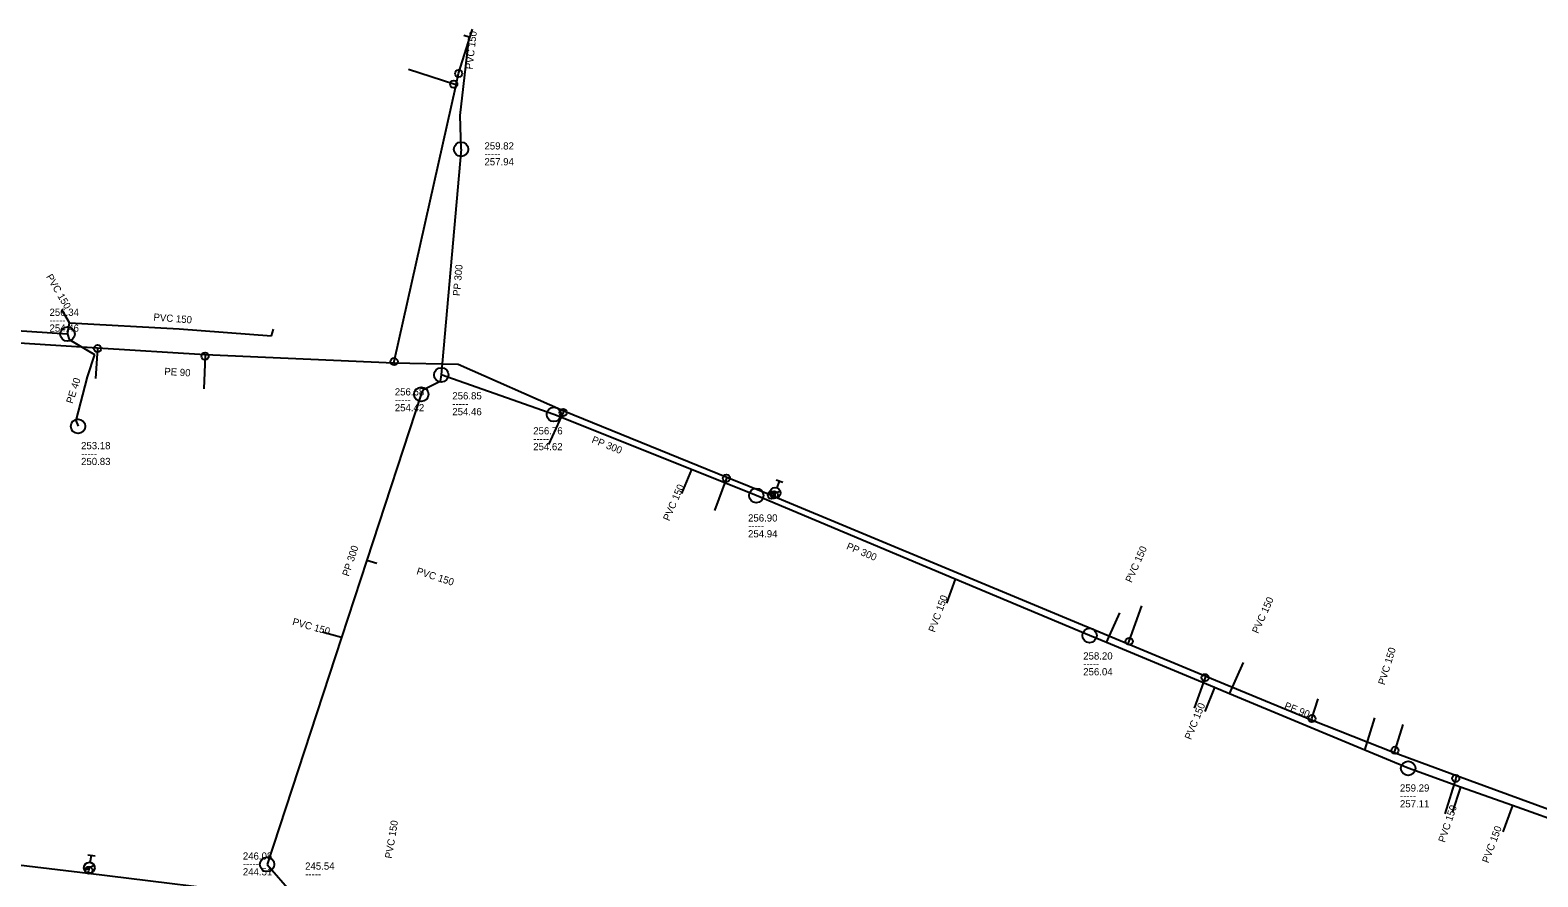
# Model space of a CAD drawing. Extents: x -771681 to -770485, y -1050143 to -1049574.
# Drawn here: x -771300.2 to -771090.5, y -1049871.3 to -1049753.6 of the extents above; entities that cross this region are included whole.
import ezdxf

# ---------------------------------------------------------------- set-up
doc = ezdxf.new("R2010")
doc.units = 0
doc.layers.add('Level 0', color=7, linetype='Continuous')

msp = doc.modelspace()

# ---------------------------------------------------------------- linework, layer by layer
at = {"layer": 'Level 0'}
for p, q in [((-771240.59, -1049759.6), (-771238.68, -1049753.42)), ((-771239.11, -1049754.55), (-771239.88, -1049754.31)), ((-771240.37, -1049765.43), (-771239.11, -1049754.55)), ((-771241.28, -1049761.08), (-771247.56, -1049759.02)), ((-771240.95, -1049761.19), (-771240.59, -1049759.6)), ((-771249.57, -1049799.67), (-771240.95, -1049761.19)), ((-771240.95, -1049761.19), (-771241.28, -1049761.08)), ((-771240.25, -1049770.14), (-771240.37, -1049765.43)), ((-771240.25, -1049770.14), (-771243.01, -1049801.52)), ((-771294.71, -1049794.27), (-771295.76, -1049792.48)), ((-771294.99, -1049795.85), (-771294.71, -1049794.27)), ((-771294.71, -1049794.27), (-771279.45, -1049795.12)), ((-771294.99, -1049795.85), (-771316.81, -1049794.4)), ((-771294.99, -1049795.85), (-771294.74, -1049796.6)), ((-771279.45, -1049795.12), (-771266.62, -1049796.09)), ((-771266.62, -1049796.09), (-771266.32, -1049795.18)), ((-771301.72, -1049797.07), (-771290.8, -1049797.76)), ((-771294.74, -1049796.6), (-771291.24, -1049798.67)), ((-771290.81, -1049797.86), (-771291.08, -1049802)), ((-771290.8, -1049797.76), (-771290.81, -1049797.86)), ((-771290.8, -1049797.76), (-771275.85, -1049798.67)), ((-771291.24, -1049798.67), (-771292.24, -1049801.78)), ((-771275.86, -1049798.92), (-771276.02, -1049803.46)), ((-771275.85, -1049798.67), (-771275.86, -1049798.92)), ((-771275.85, -1049798.67), (-771249.61, -1049799.84)), ((-771249.61, -1049799.84), (-771249.57, -1049799.67)), ((-771249.61, -1049799.84), (-771240.67, -1049800.01)), ((-771240.67, -1049800.01), (-771225.96, -1049806.53)), ((-771292.24, -1049801.78), (-771293.84, -1049807.85)), ((-771243.18, -1049802.43), (-771245.55, -1049803.64)), ((-771243.01, -1049801.52), (-771243.18, -1049802.43)), ((-771227.35, -1049807.02), (-771243.01, -1049801.52)), ((-771245.79, -1049804.22), (-771253.35, -1049827.27)), ((-771245.55, -1049803.64), (-771245.79, -1049804.22)), ((-771226.06, -1049806.75), (-771228.1, -1049811.18)), ((-771225.96, -1049806.53), (-771226.06, -1049806.75)), ((-771225.96, -1049806.53), (-771203.3, -1049815.73)), ((-771293.84, -1049807.85), (-771293.52, -1049808.67)), ((-771208.19, -1049814.7), (-771227.35, -1049807.02)), ((-771208.19, -1049814.7), (-771209.62, -1049818.03)), ((-771199.2, -1049818.3), (-771208.19, -1049814.7)), ((-771203.36, -1049815.88), (-771205.03, -1049820.36)), ((-771203.3, -1049815.73), (-771203.36, -1049815.88)), ((-771203.3, -1049815.73), (-771197.1, -1049818.25)), ((-771196.44, -1049816.11), (-771195.5, -1049816.46)), ((-771196.31, -1049817.23), (-771195.97, -1049816.29)), ((-771171.54, -1049829.92), (-771199.2, -1049818.3)), ((-771197.28, -1049818.16), (-771195.86, -1049817.7)), ((-771197.1, -1049818.25), (-771196.8, -1049818.37)), ((-771196.8, -1049818.37), (-771196.7, -1049818.2)), ((-771196.8, -1049818.37), (-771147.47, -1049838.94)), ((-771196.7, -1049818.2), (-771196.57, -1049817.93)), ((-771253.35, -1049827.27), (-771256.89, -1049838.05)), ((-771253.35, -1049827.27), (-771251.96, -1049827.72)), ((-771171.54, -1049829.92), (-771172.73, -1049833.25)), ((-771152.85, -1049837.77), (-771171.54, -1049829.92)), ((-771147.34, -1049838.58), (-771145.56, -1049833.63)), ((-771150.47, -1049838.76), (-771148.62, -1049834.61)), ((-771256.89, -1049838.05), (-771267.23, -1049869.61)), ((-771256.89, -1049838.05), (-771259.57, -1049837.31)), ((-771150.47, -1049838.76), (-771152.85, -1049837.77)), ((-771135.46, -1049845.02), (-771150.47, -1049838.76)), ((-771147.47, -1049838.94), (-771147.34, -1049838.58)), ((-771147.47, -1049838.94), (-771136.7, -1049843.41)), ((-771133.37, -1049845.89), (-771131.42, -1049841.54)), ((-771136.78, -1049843.63), (-771138.32, -1049847.89)), ((-771136.7, -1049843.41), (-771136.78, -1049843.63)), ((-771136.7, -1049843.41), (-771121.99, -1049849.51)), ((-771135.46, -1049845.02), (-771136.8, -1049848.32)), ((-771133.37, -1049845.89), (-771135.46, -1049845.02)), ((-771114.57, -1049853.74), (-771133.37, -1049845.89)), ((-771121.93, -1049849.32), (-771121.07, -1049846.59)), ((-771121.99, -1049849.51), (-771121.93, -1049849.32)), ((-771121.99, -1049849.51), (-771110.47, -1049854.05)), ((-771114.57, -1049853.74), (-771113.19, -1049849.2)), ((-771110.37, -1049853.73), (-771109.24, -1049850.17)), ((-771108.54, -1049856.24), (-771114.57, -1049853.74)), ((-771110.47, -1049854.05), (-771110.37, -1049853.73)), ((-771110.47, -1049854.05), (-771101.81, -1049857.24)), ((-771101.26, -1049858.85), (-771108.54, -1049856.24)), ((-771101.93, -1049857.64), (-771103.42, -1049862.56)), ((-771101.26, -1049858.85), (-771102.43, -1049862.37)), ((-771101.81, -1049857.24), (-771101.93, -1049857.64)), ((-771101.81, -1049857.24), (-771081.01, -1049864.88)), ((-771094.02, -1049861.43), (-771101.26, -1049858.85)), ((-771094.02, -1049861.43), (-771095.38, -1049865.08)), ((-771085.49, -1049864.48), (-771094.02, -1049861.43)), ((-771305.7, -1049869.19), (-771292.13, -1049870.85)), ((-771292.61, -1049870.42), (-771291.29, -1049869.72)), ((-771292.14, -1049868.26), (-771291.15, -1049868.43)), ((-771291.82, -1049869.33), (-771291.65, -1049868.35)), ((-771267.23, -1049869.61), (-771263.73, -1049873.6)), ((-771292.13, -1049870.85), (-771292.03, -1049870.43)), ((-771292.13, -1049870.85), (-771266.5, -1049873.98)), ((-771292.03, -1049870.43), (-771291.95, -1049870.07))]:
    msp.add_line(p, q, dxfattribs=at)
for centre, radius in [((-771241.28, -1049761.08), 0.5), ((-771240.59, -1049759.6), 0.5), ((-771240.25, -1049770.14), 1), ((-771294.99, -1049795.85), 1), ((-771290.81, -1049797.86), 0.5), ((-771275.86, -1049798.92), 0.5), ((-771249.57, -1049799.67), 0.5), ((-771243.01, -1049801.52), 1), ((-771245.79, -1049804.22), 1), ((-771227.35, -1049807.02), 1), ((-771226.06, -1049806.75), 0.5), ((-771293.52, -1049808.67), 1), ((-771203.36, -1049815.88), 0.5), ((-771199.2, -1049818.3), 1), ((-771196.57, -1049817.93), 0.75), ((-771197.1, -1049818.25), 0.5), ((-771196.7, -1049818.2), 0.5), ((-771152.85, -1049837.77), 1), ((-771147.34, -1049838.58), 0.5), ((-771136.78, -1049843.63), 0.5), ((-771121.93, -1049849.32), 0.5), ((-771110.37, -1049853.73), 0.5), ((-771108.54, -1049856.24), 1), ((-771101.93, -1049857.64), 0.5), ((-771291.95, -1049870.07), 0.75), ((-771267.23, -1049869.61), 1), ((-771292.03, -1049870.43), 0.5)]:
    msp.add_circle(centre, radius, dxfattribs=at)

# ---------------------------------------------------------------- texts
for s, rotation, p in [('PVC 150', 83.394, (-771238.67, -1049759.07)), ('PVC 150', 300.396, (-771298.01, -1049787.86)), ('PP 300', 84.974, (-771240.41, -1049790.58)), ('PVC 150', 355.676, (-771283.06, -1049793.96)), ('PE 90', 356.517, (-771281.55, -1049801.52)), ('PE 40', 72.175, (-771294.26, -1049805.59)), ('PP 300', 338.177, (-771222.18, -1049810.91)), ('PVC 150', 66.76, (-771211.3, -1049821.92)), ('PP 300', 71.821, (-771255.87, -1049829.62)), ('PP 300', 337.217, (-771186.75, -1049825.72)), ('PVC 150', 65.973, (-771147.01, -1049830.5)), ('PVC 150', 342.061, (-771246.53, -1049829.22)), ('PVC 150', 70.335, (-771174.36, -1049837.41)), ('PVC 150', 65.854, (-771129.4, -1049837.58)), ('PVC 150', 344.564, (-771263.79, -1049836.28)), ('PVC 150', 73.093, (-771111.8, -1049844.73)), ('PVC 150', 67.9, (-771138.75, -1049852.35)), ('PE 90', 338.491, (-771125.85, -1049847.91)), ('PVC 150', 71.614, (-771103.44, -1049866.64)), ('PVC 150', 80.665, (-771249.88, -1049868.85)), ('PVC 150', 69.564, (-771097.37, -1049869.5))]:
    msp.add_text(s, height=1, rotation=rotation, dxfattribs=at).set_placement(p)
for s, p in [('259.82', (-771237, -1049770.17)), ('-----', (-771237, -1049771.27)), ('257.94', (-771237, -1049772.37)), ('-----', (-771297.49, -1049794.41)), ('256.34', (-771297.49, -1049793.31)), ('254.46', (-771297.49, -1049795.51)), ('256.68', (-771249.47, -1049804.38)), ('256.85', (-771241.47, -1049804.93)), ('-----', (-771249.47, -1049805.48)), ('254.42', (-771249.47, -1049806.58)), ('-----', (-771241.47, -1049806.03)), ('254.46', (-771241.47, -1049807.13)), ('256.76', (-771230.22, -1049809.8)), ('253.18', (-771293.1, -1049811.86)), ('-----', (-771230.22, -1049810.9)), ('254.62', (-771230.22, -1049812)), ('-----', (-771293.1, -1049812.96)), ('250.83', (-771293.1, -1049814.06)), ('256.90', (-771200.34, -1049821.92)), ('-----', (-771200.34, -1049823.02)), ('254.94', (-771200.34, -1049824.12)), ('258.20', (-771153.73, -1049841.11)), ('-----', (-771153.73, -1049842.21)), ('256.04', (-771153.73, -1049843.31)), ('259.29', (-771109.68, -1049859.48)), ('-----', (-771109.68, -1049860.58)), ('257.11', (-771109.68, -1049861.68)), ('-----', (-771270.6, -1049870.04)), ('246.08', (-771270.6, -1049868.94)), ('245.54', (-771261.94, -1049870.34)), ('244.51', (-771270.6, -1049871.14)), ('-----', (-771261.94, -1049871.44))]:
    msp.add_text(s, height=1, dxfattribs=at).set_placement(p)

doc.saveas('drawing.dxf')
